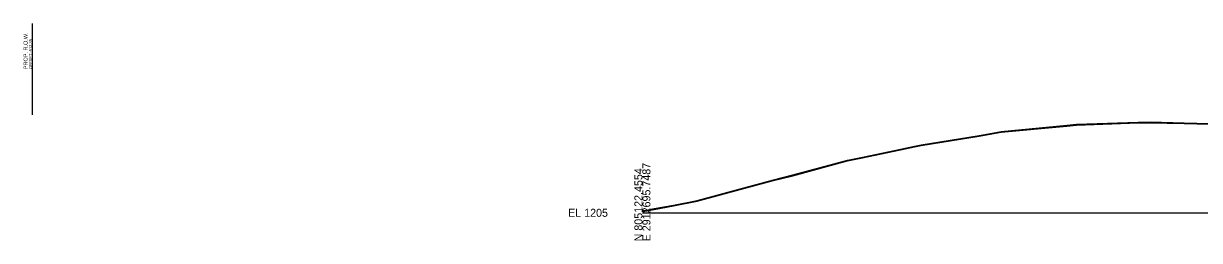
# Model space of a CAD drawing. Extents: x -231 to 794, y -10 to 23644.
# Drawn here: x -216.5 to 194.9, y 6490.3 to 6566.2 of the extents above; entities that cross this region are included whole.
import ezdxf

# ---------------------------------------------------------------- set-up
doc = ezdxf.new("R2010")
doc.units = 0
for name, color, linetype in [('DESIGN - ROW - Right-of-Way and Easement Labels', 7, 'Continuous'), ('DESIGN - ROW - Right-of-Way Linework', 7, 'Continuous'), ('DESIGN - SHEET - Light Grid', 7, 'Continuous'), ('SURVEY - GROUND - Bottom of Topsoil Layer', 7, 'Continuous'), ('SURVEY - GROUND - Top of Ground', 7, 'Continuous')]:
    doc.layers.add(name, color=color, linetype=linetype)

msp = doc.modelspace()

# ---------------------------------------------------------------- linework, layer by layer
at = {"layer": 'DESIGN - ROW - Right-of-Way Linework'}
msp.add_line((-213.35, 6534.25), (-213.35, 6566.25), dxfattribs=at)
at = {"layer": 'DESIGN - SHEET - Light Grid'}
msp.add_line((0, 6500), (300, 6500), dxfattribs=at)
at = {"layer": 'SURVEY - GROUND - Bottom of Topsoil Layer'}
for p, q in [((125.48, 6528.22), (148.44, 6530.37)), ((148.44, 6530.37), (151.85, 6530.72)), ((151.85, 6530.72), (173.44, 6531.44)), ((173.44, 6531.44), (177.69, 6531.54)), ((177.69, 6531.54), (189.56, 6531.28)), ((189.56, 6531.28), (202.97, 6530.93)), ((97.5, 6523.56), (117.77, 6526.78)), ((117.77, 6526.78), (125.48, 6528.22)), ((77.04, 6519.22), (90.25, 6522.04)), ((90.25, 6522.04), (95.16, 6523.03)), ((95.16, 6523.03), (97.5, 6523.56)), ((52.64, 6512.98), (71.8, 6518.14)), ((71.8, 6518.14), (77.04, 6519.22)), ((45.83, 6511.26), (52.64, 6512.98)), ((35.54, 6508.49), (45.83, 6511.26)), ((19.18, 6504.07), (35.54, 6508.49)), ((0, 6500.5), (0.9, 6500.58)), ((0.9, 6500.58), (4.13, 6501.21)), ((4.13, 6501.21), (10.84, 6502.39)), ((10.84, 6502.39), (19.18, 6504.07))]:
    msp.add_line(p, q, dxfattribs=at)
at = {"layer": 'SURVEY - GROUND - Top of Ground'}
msp.add_lwpolyline([(0, 6500.75), (0.9, 6500.83), (4.13, 6501.46), (10.84, 6502.64), (19.18, 6504.32), (35.54, 6508.74), (45.83, 6511.51), (52.64, 6513.23), (71.8, 6518.39), (77.04, 6519.47), (90.25, 6522.29), (95.16, 6523.28), (97.5, 6523.81), (117.77, 6527.03), (125.48, 6528.47), (148.44, 6530.62), (151.85, 6530.97), (173.44, 6531.69), (177.69, 6531.79), (189.56, 6531.53), (202.97, 6531.18)], dxfattribs=at)

# ---------------------------------------------------------------- texts
at = {"layer": 'DESIGN - ROW - Right-of-Way and Easement Labels'}
for s, height, p in [('PROP. R.O.W.', 1.4, (-215.1, 6550.25)), ('OFFSET -513.35', 1, (-213.6, 6550.25))]:
    msp.add_text(s, height=height, rotation=90, dxfattribs=at).set_placement(p)
at = {"layer": 'DESIGN - SHEET - Light Grid'}
for s, p in [('E 2912695.7487', (2.8, 6490)), ('N 805122.4554', (0, 6490))]:
    msp.add_text(s, height=2.8, rotation=90, dxfattribs=at).set_placement(p)
msp.add_text('EL 1205', height=2.8, dxfattribs=at).set_placement((-26, 6498.6))

doc.saveas('drawing.dxf')
